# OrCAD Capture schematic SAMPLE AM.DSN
size A
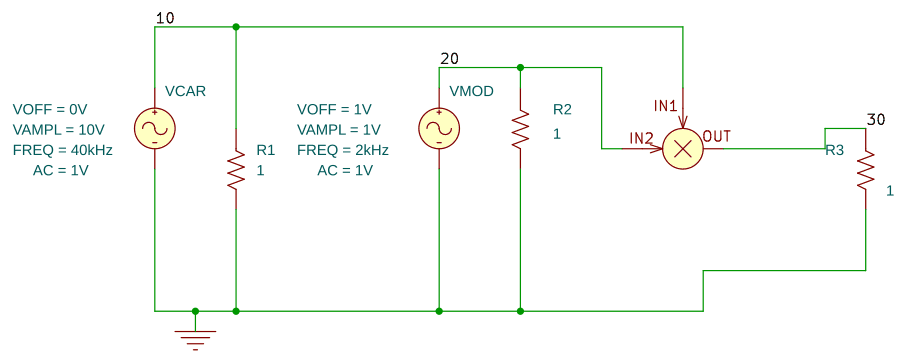
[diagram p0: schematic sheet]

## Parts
MULT1  MULT
R1  1  [AX/RC05]
R2  1  [AX/RC05]
R3  1  [AX/RC05]
VCAR  VSIN
VMOD  VSIN

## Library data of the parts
MULT1 = MULT
R1-R3 = R
VCAR = VSIN: AC: 1V; FREQ: 40kHz; VAMPL: 10V; VOFF: 0V
VMOD = VSIN: AC: 1V; FREQ: 2kHz; VAMPL: 1V; VOFF: 1V

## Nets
0: R1.2 R2.2 R3.2 VCAR.2(-) VMOD.2(-)
10: MULT1.1(IN1) R1.1 VCAR.1(+)
20: MULT1.3(IN2) R2.1 VMOD.1(+)
30: MULT1.5(OUT) R3.1
